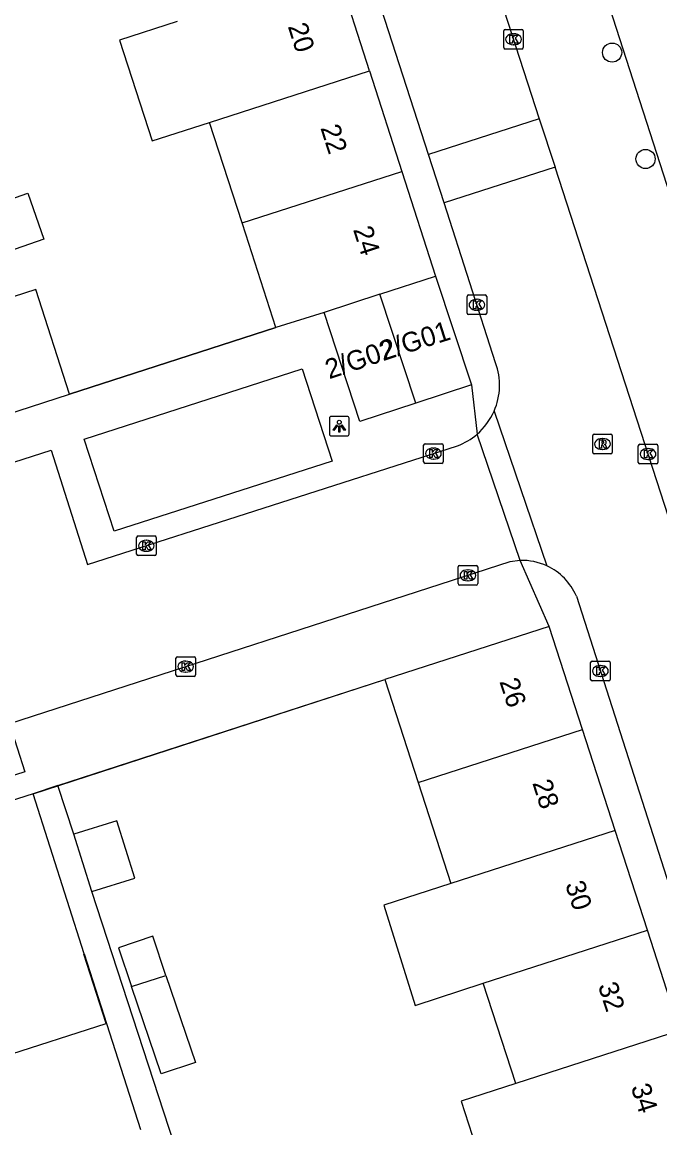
# Model space of a CAD drawing. Extents: x 159377 to 159983, y 382996 to 383595.
# Drawn here: x 159569 to 159601.6, y 383184.3 to 383240.7 of the extents above; entities that cross this region are included whole.
import ezdxf

# ---------------------------------------------------------------- set-up
doc = ezdxf.new("R2010")
doc.units = 0
for name, color, linetype in [('IMGEO_Boom', 7, 'Continuous'), ('IMGEO_Kolk', 7, 'Continuous'), ('IMGEO_Lichtpunt', 7, 'Continuous'), ('IMGEO_Muur', 7, 'Continuous'), ('IMGEO_Pand', 7, 'Continuous'), ('IMGEO_Pand_nummerreeks', 7, 'Continuous'), ('IMGEO_Rijbaan_lokaal_open', 7, 'Continuous'), ('IMGEO_Rioolput', 7, 'Continuous'), ('IMGEO_Voetpad_open', 7, 'Continuous')]:
    doc.layers.add(name, color=color, linetype=linetype)

msp = doc.modelspace()

# ---------------------------------------------------------------- linework, layer by layer
at = {"layer": 'IMGEO_Boom'}
for centre in [(159599.134, 383239.138), (159600.842, 383233.709)]:
    msp.add_circle(centre, 0.489, dxfattribs=at)
at = {"layer": 'IMGEO_Kolk'}
for p, q in [((159593.602, 383239.393), (159593.602, 383240.245)), ((159593.677, 383240.319), (159594.529, 383240.319)), ((159594.09, 383240.099), (159594.115, 383240.099)), ((159594.603, 383240.245), (159594.603, 383239.393)), ((159594.113, 383239.539), (159594.088, 383239.539)), ((159594.529, 383239.319), (159593.677, 383239.319)), ((159591.734, 383225.841), (159591.734, 383226.693)), ((159591.809, 383226.767), (159592.661, 383226.767)), ((159592.222, 383226.547), (159592.247, 383226.547)), ((159592.735, 383226.693), (159592.735, 383225.841)), ((159592.245, 383225.987), (159592.22, 383225.987)), ((159592.661, 383225.767), (159591.809, 383225.767)), ((159589.59, 383219.174), (159590.442, 383219.174)), ((159600.545, 383219.15), (159601.397, 383219.15)), ((159589.515, 383218.248), (159589.515, 383219.1)), ((159590.003, 383218.954), (159590.028, 383218.954)), ((159590.516, 383219.1), (159590.516, 383218.248)), ((159600.47, 383218.224), (159600.47, 383219.076)), ((159600.958, 383218.93), (159600.983, 383218.93)), ((159601.471, 383219.076), (159601.471, 383218.224)), ((159590.442, 383218.174), (159589.59, 383218.174)), ((159590.026, 383218.394), (159590.001, 383218.394)), ((159601.397, 383218.15), (159600.545, 383218.15)), ((159600.981, 383218.37), (159600.956, 383218.37)), ((159574.865, 383213.542), (159574.865, 383214.394)), ((159574.94, 383214.468), (159575.792, 383214.468)), ((159575.353, 383214.248), (159575.378, 383214.248)), ((159575.866, 383214.394), (159575.866, 383213.542)), ((159575.376, 383213.688), (159575.351, 383213.688)), ((159575.792, 383213.468), (159574.94, 383213.468)), ((159591.349, 383212.961), (159592.201, 383212.961)), ((159591.274, 383212.035), (159591.274, 383212.887)), ((159591.762, 383212.741), (159591.787, 383212.741)), ((159592.275, 383212.887), (159592.275, 383212.035)), ((159592.201, 383211.961), (159591.349, 383211.961)), ((159591.785, 383212.181), (159591.76, 383212.181)), ((159576.873, 383207.375), (159576.873, 383208.227)), ((159576.948, 383208.301), (159577.8, 383208.301)), ((159577.361, 383208.081), (159577.386, 383208.081)), ((159577.874, 383208.227), (159577.874, 383207.375)), ((159598.037, 383207.152), (159598.037, 383208.004)), ((159598.112, 383208.078), (159598.964, 383208.078)), ((159598.525, 383207.858), (159598.55, 383207.858)), ((159599.038, 383208.004), (159599.038, 383207.152)), ((159577.8, 383207.301), (159576.948, 383207.301)), ((159577.384, 383207.521), (159577.359, 383207.521)), ((159598.548, 383207.298), (159598.523, 383207.298)), ((159598.964, 383207.078), (159598.112, 383207.078))]:
    msp.add_line(p, q, dxfattribs=at)
for points in [[(159593.602, 383239.393), (159593.602, 383240.245)], [(159593.677, 383240.319), (159594.529, 383240.319)], [(159593.923, 383240.019), (159594.046, 383240.019), (159594.046, 383239.868), (159594.176, 383240.019), (159594.34, 383240.019), (159594.194, 383239.868), (159594.347, 383239.619), (159594.195, 383239.619), (159594.11, 383239.783), (159594.046, 383239.716), (159594.046, 383239.619), (159593.923, 383239.619), (159593.923, 383240.019)], [(159594.603, 383240.245), (159594.603, 383239.393)], [(159594.529, 383239.319), (159593.677, 383239.319)], [(159591.734, 383225.841), (159591.734, 383226.693)], [(159591.809, 383226.767), (159592.661, 383226.767)], [(159592.055, 383226.467), (159592.178, 383226.467), (159592.178, 383226.316), (159592.308, 383226.467), (159592.472, 383226.467), (159592.326, 383226.316), (159592.479, 383226.067), (159592.327, 383226.067), (159592.242, 383226.231), (159592.178, 383226.164), (159592.178, 383226.067), (159592.055, 383226.067), (159592.055, 383226.467)], [(159592.735, 383226.693), (159592.735, 383225.841)], [(159592.661, 383225.767), (159591.809, 383225.767)], [(159589.59, 383219.174), (159590.442, 383219.174)], [(159600.545, 383219.15), (159601.397, 383219.15)], [(159589.515, 383218.248), (159589.515, 383219.1)], [(159589.836, 383218.874), (159589.959, 383218.874), (159589.959, 383218.723), (159590.089, 383218.874), (159590.253, 383218.874), (159590.107, 383218.723), (159590.26, 383218.474), (159590.108, 383218.474), (159590.023, 383218.638), (159589.959, 383218.571), (159589.959, 383218.474), (159589.836, 383218.474), (159589.836, 383218.874)], [(159590.516, 383219.1), (159590.516, 383218.248)], [(159600.47, 383218.224), (159600.47, 383219.076)], [(159600.791, 383218.85), (159600.914, 383218.85), (159600.914, 383218.699), (159601.044, 383218.85), (159601.208, 383218.85), (159601.062, 383218.699), (159601.215, 383218.45), (159601.063, 383218.45), (159600.978, 383218.614), (159600.914, 383218.547), (159600.914, 383218.45), (159600.791, 383218.45), (159600.791, 383218.85)], [(159601.471, 383219.076), (159601.471, 383218.224)], [(159590.442, 383218.174), (159589.59, 383218.174)], [(159601.397, 383218.15), (159600.545, 383218.15)], [(159574.865, 383213.542), (159574.865, 383214.394)], [(159574.94, 383214.468), (159575.792, 383214.468)], [(159575.186, 383214.168), (159575.309, 383214.168), (159575.309, 383214.017), (159575.439, 383214.168), (159575.603, 383214.168), (159575.457, 383214.017), (159575.61, 383213.768), (159575.458, 383213.768), (159575.373, 383213.932), (159575.309, 383213.865), (159575.309, 383213.768), (159575.186, 383213.768), (159575.186, 383214.168)], [(159575.866, 383214.394), (159575.866, 383213.542)], [(159575.792, 383213.468), (159574.94, 383213.468)], [(159591.349, 383212.961), (159592.201, 383212.961)], [(159591.274, 383212.035), (159591.274, 383212.887)], [(159591.595, 383212.661), (159591.718, 383212.661), (159591.718, 383212.51), (159591.848, 383212.661), (159592.012, 383212.661), (159591.866, 383212.51), (159592.019, 383212.261), (159591.867, 383212.261), (159591.782, 383212.425), (159591.718, 383212.358), (159591.718, 383212.261), (159591.595, 383212.261), (159591.595, 383212.661)], [(159592.275, 383212.887), (159592.275, 383212.035)], [(159592.201, 383211.961), (159591.349, 383211.961)], [(159576.873, 383207.375), (159576.873, 383208.227)], [(159576.948, 383208.301), (159577.8, 383208.301)], [(159577.194, 383208.001), (159577.317, 383208.001), (159577.317, 383207.85), (159577.447, 383208.001), (159577.611, 383208.001), (159577.465, 383207.85), (159577.618, 383207.601), (159577.466, 383207.601), (159577.381, 383207.765), (159577.317, 383207.698), (159577.317, 383207.601), (159577.194, 383207.601), (159577.194, 383208.001)], [(159577.874, 383208.227), (159577.874, 383207.375)], [(159598.037, 383207.152), (159598.037, 383208.004)], [(159598.112, 383208.078), (159598.964, 383208.078)], [(159599.038, 383208.004), (159599.038, 383207.152)], [(159577.8, 383207.301), (159576.948, 383207.301)], [(159598.358, 383207.778), (159598.481, 383207.778), (159598.481, 383207.627), (159598.611, 383207.778), (159598.775, 383207.778), (159598.629, 383207.627), (159598.782, 383207.378), (159598.63, 383207.378), (159598.545, 383207.542), (159598.481, 383207.475), (159598.481, 383207.378), (159598.358, 383207.378), (159598.358, 383207.778)], [(159598.964, 383207.078), (159598.112, 383207.078)]]:
    msp.add_lwpolyline(points, dxfattribs=at)
for centre, start, end in [((159593.679, 383240.243), 91.552, 178.448), ((159593.679, 383240.243), 91.552, 178.448), ((159594.527, 383240.243), 1.552, 88.448), ((159594.527, 383240.243), 1.552, 88.448), ((159593.679, 383239.395), 181.552, 268.448), ((159593.679, 383239.395), 181.552, 268.448), ((159594.527, 383239.395), 271.552, 358.448), ((159594.527, 383239.395), 271.552, 358.448), ((159591.811, 383226.691), 91.552, 178.448), ((159591.811, 383226.691), 91.552, 178.448), ((159592.659, 383226.691), 1.552, 88.448), ((159592.659, 383226.691), 1.552, 88.448), ((159591.811, 383225.843), 181.552, 268.448), ((159591.811, 383225.843), 181.552, 268.448), ((159592.659, 383225.843), 271.552, 358.448), ((159592.659, 383225.843), 271.552, 358.448), ((159589.592, 383219.098), 91.552, 178.448), ((159589.592, 383219.098), 91.552, 178.448), ((159590.44, 383219.098), 1.552, 88.448), ((159590.44, 383219.098), 1.552, 88.448), ((159600.547, 383219.074), 91.552, 178.448), ((159600.547, 383219.074), 91.552, 178.448), ((159601.395, 383219.074), 1.552, 88.448), ((159601.395, 383219.074), 1.552, 88.448), ((159589.592, 383218.25), 181.552, 268.448), ((159589.592, 383218.25), 181.552, 268.448), ((159590.44, 383218.25), 271.552, 358.448), ((159590.44, 383218.25), 271.552, 358.448), ((159600.547, 383218.226), 181.552, 268.448), ((159600.547, 383218.226), 181.552, 268.448), ((159601.395, 383218.226), 271.552, 358.448), ((159601.395, 383218.226), 271.552, 358.448), ((159574.942, 383214.392), 91.552, 178.448), ((159574.942, 383214.392), 91.552, 178.448), ((159575.79, 383214.392), 1.552, 88.448), ((159575.79, 383214.392), 1.552, 88.448), ((159574.942, 383213.544), 181.552, 268.448), ((159574.942, 383213.544), 181.552, 268.448), ((159575.79, 383213.544), 271.552, 358.448), ((159575.79, 383213.544), 271.552, 358.448), ((159591.351, 383212.885), 91.552, 178.448), ((159591.351, 383212.885), 91.552, 178.448), ((159592.199, 383212.885), 1.552, 88.448), ((159592.199, 383212.885), 1.552, 88.448), ((159591.351, 383212.037), 181.552, 268.448), ((159591.351, 383212.037), 181.552, 268.448), ((159592.199, 383212.037), 271.552, 358.448), ((159592.199, 383212.037), 271.552, 358.448), ((159576.95, 383208.225), 91.552, 178.448), ((159576.95, 383208.225), 91.552, 178.448), ((159577.798, 383208.225), 1.552, 88.448), ((159577.798, 383208.225), 1.552, 88.448), ((159598.114, 383208.002), 91.552, 178.448), ((159598.114, 383208.002), 91.552, 178.448), ((159598.962, 383208.002), 1.552, 88.448), ((159598.962, 383208.002), 1.552, 88.448), ((159576.95, 383207.377), 181.552, 268.448), ((159576.95, 383207.377), 181.552, 268.448), ((159577.798, 383207.377), 271.552, 358.448), ((159577.798, 383207.377), 271.552, 358.448), ((159598.114, 383207.154), 181.552, 268.448), ((159598.114, 383207.154), 181.552, 268.448), ((159598.962, 383207.154), 271.552, 358.448), ((159598.962, 383207.154), 271.552, 358.448)]:
    msp.add_arc(centre, 0.0765, start, end, dxfattribs=at)
for centre, major_axis, ratio, start_param, end_param in [((159594.089, 383239.819), (-0.387, 0.002), 0.722429, 4.712389, 7.853982), ((159594.114, 383239.819), (-0.39, 0.002), 0.717154, 1.570796, 4.712389), ((159592.221, 383226.267), (-0.387, 0.002), 0.722429, 4.712389, 7.853982), ((159592.246, 383226.267), (-0.39, 0.002), 0.717154, 1.570796, 4.712389), ((159590.002, 383218.674), (-0.387, 0.002), 0.722429, 4.712389, 7.853982), ((159590.027, 383218.674), (-0.39, 0.002), 0.717154, 1.570796, 4.712389), ((159600.957, 383218.65), (-0.387, 0.002), 0.722429, 4.712389, 7.853982), ((159600.982, 383218.65), (-0.39, 0.002), 0.717154, 1.570796, 4.712389), ((159575.352, 383213.968), (-0.387, 0.002), 0.722429, 4.712389, 7.853982), ((159575.377, 383213.968), (-0.39, 0.002), 0.717154, 1.570796, 4.712389), ((159591.761, 383212.461), (-0.387, 0.002), 0.722429, 4.712389, 7.853982), ((159591.786, 383212.461), (-0.39, 0.002), 0.717154, 1.570796, 4.712389), ((159577.36, 383207.801), (-0.387, 0.002), 0.722429, 4.712389, 7.853982), ((159577.385, 383207.801), (-0.39, 0.002), 0.717154, 1.570796, 4.712389), ((159598.524, 383207.578), (-0.387, 0.002), 0.722429, 4.712389, 7.853982), ((159598.549, 383207.578), (-0.39, 0.002), 0.717154, 1.570796, 4.712389)]:
    msp.add_ellipse(centre, major_axis=major_axis, ratio=ratio, start_param=start_param, end_param=end_param, dxfattribs=at)
at = {"layer": 'IMGEO_Lichtpunt'}
for p, q in [((159584.712, 383220.474), (159584.712, 383219.667)), ((159584.712, 383220.474), (159584.712, 383219.667)), ((159585.614, 383220.569), (159584.806, 383220.569)), ((159585.614, 383220.569), (159584.806, 383220.569)), ((159585.708, 383219.667), (159585.708, 383220.474)), ((159585.708, 383219.667), (159585.708, 383220.474)), ((159584.806, 383219.573), (159585.614, 383219.573)), ((159584.806, 383219.573), (159585.614, 383219.573))]:
    msp.add_line(p, q, dxfattribs=at)
for points in [[(159585.086, 383220.138), (159585.125, 383220.11), (159584.937, 383219.848), (159584.899, 383219.875), (159585.086, 383220.138)], [(159585.188, 383220.09), (159585.235, 383220.09), (159585.235, 383219.768), (159585.188, 383219.768), (159585.188, 383220.09)], [(159585.298, 383220.11), (159585.336, 383220.137), (159585.523, 383219.875), (159585.484, 383219.847), (159585.298, 383220.11)]]:
    msp.add_lwpolyline(points, dxfattribs=at)
msp.add_circle((159585.211, 383220.272), 0.0994, dxfattribs=at)
for centre, start, end in [((159584.806, 383220.474), 90, 180), ((159584.806, 383220.474), 90, 180), ((159585.614, 383220.474), 0, 90), ((159585.614, 383220.474), 0, 90), ((159584.806, 383219.667), 180, 270), ((159584.806, 383219.667), 180, 270), ((159585.614, 383219.667), 270, 0), ((159585.614, 383219.667), 270, 360)]:
    msp.add_arc(centre, 0.0946, start, end, dxfattribs=at)
at = {"layer": 'IMGEO_Muur'}
for points in [[(159571.447, 383221.705), (159581.974, 383225.106)], [(159569.587, 383201.314), (159587.539, 383207.143)]]:
    msp.add_lwpolyline(points, dxfattribs=at)
at = {"layer": 'IMGEO_Pand'}
for points in [[(159586.752, 383238.201), (159585.097, 383243.354)], [(159576.933, 383240.724), (159574, 383239.779), (159575.659, 383234.63), (159578.595, 383235.575)], [(159578.595, 383235.575), (159586.752, 383238.201)], [(159586.752, 383238.201), (159588.402, 383233.069)], [(159580.251, 383230.443), (159578.595, 383235.575)], [(159580.251, 383230.443), (159588.402, 383233.069)], [(159588.402, 383233.069), (159590.116, 383227.736)], [(159569.319, 383231.964), (159570.14, 383229.617), (159567.941, 383228.848), (159567.12, 383231.195), (159569.319, 383231.964)], [(159581.974, 383225.106), (159580.438, 383229.865), (159580.251, 383230.443)], [(159587.276, 383226.815), (159590.116, 383227.736)], [(159590.116, 383227.736), (159591.966, 383222.185)], [(159571.447, 383221.705), (159569.717, 383227.049), (159567.34, 383226.283)], [(159587.276, 383226.815), (159584.434, 383225.871)], [(159589.114, 383221.244), (159587.276, 383226.815)], [(159584.434, 383225.871), (159581.974, 383225.106)], [(159589.114, 383221.244), (159586.261, 383220.303), (159584.434, 383225.871)], [(159565.818, 383223.436), (159566.861, 383220.219), (159571.447, 383221.705)], [(159591.966, 383222.185), (159589.114, 383221.244)], [(159595.914, 383209.856), (159587.539, 383207.143)], [(159597.617, 383204.596), (159595.914, 383209.856)], [(159587.539, 383207.143), (159589.24, 383201.89)], [(159589.24, 383201.89), (159597.617, 383204.596)], [(159599.287, 383199.441), (159597.617, 383204.596)], [(159589.24, 383201.89), (159590.909, 383196.737)], [(159569.587, 383201.314), (159564.189, 383199.583)], [(159572.197, 383193.137), (159569.587, 383201.314)], [(159572.587, 383196.317), (159574.778, 383197.01), (159573.852, 383199.938), (159571.66, 383199.245)], [(159599.287, 383199.441), (159590.909, 383196.737)], [(159600.938, 383194.343), (159599.287, 383199.441)], [(159572.587, 383196.317), (159571.66, 383199.245)], [(159590.909, 383196.737), (159587.489, 383195.62), (159589.076, 383190.501), (159592.56, 383191.638)], [(159592.56, 383191.638), (159600.938, 383194.343)], [(159602.595, 383189.226), (159600.938, 383194.343)], [(159576.366, 383192.043), (159575.689, 383194.042), (159573.939, 383193.449), (159574.608, 383191.476)], [(159568.017, 383187.893), (159573.31, 383189.59), (159572.175, 383193.13), (159572.197, 383193.137)], [(159574.608, 383191.476), (159576.366, 383192.043)], [(159576.366, 383192.043), (159577.87, 383187.603), (159576.12, 383187.011), (159574.608, 383191.476)], [(159594.217, 383186.522), (159592.56, 383191.638)], [(159602.595, 383189.226), (159594.217, 383186.522)], [(159594.217, 383186.522), (159591.435, 383185.624), (159593.118, 383180.411), (159595.904, 383181.31)]]:
    msp.add_lwpolyline(points, dxfattribs=at)
at = {"layer": 'IMGEO_Rijbaan_lokaal_open'}
for points in [[(159585.361, 383266.81), (159590.799, 383250), (159595.419, 383235.761)], [(159589.762, 383233.936), (159584.58, 383250), (159579.729, 383264.98)], [(159595.419, 383235.761), (159589.762, 383233.936)], [(159595.419, 383235.761), (159596.221, 383233.289)], [(159590.56, 383231.462), (159589.762, 383233.936)], [(159596.221, 383233.289), (159590.56, 383231.462)], [(159607.802, 383197.595), (159596.221, 383233.289)], [(159593.192, 383223.303), (159590.56, 383231.462)], [(159528.425, 383210.177), (159564.747, 383221.794), (159566.151, 383217.448), (159570.5, 383218.852), (159572.368, 383213.005), (159591.243, 383219.067)], [(159593.112, 383220.84), (159595.806, 383212.941)], [(159594.442, 383213.217), (159592.24, 383219.664)], [(159594.442, 383213.217), (159593.923, 383213.154), (159568.377, 383204.889), (159569.171, 383202.429), (159543.044, 383194.025)], [(159597.309, 383211.405), (159602.34, 383195.729)]]:
    msp.add_lwpolyline(points, dxfattribs=at)
for centre, radius, start, end in [((159590.112, 383222.17), 3.281, 336.0849, 20.1944), ((159590.045, 383222.203), 3.356, 310.8452, 336.0412), ((159590.052, 383222.187), 3.34, 290.8933, 310.9327), ((159594.544, 383210.211), 3.008, 65.1862, 91.9355), ((159594.541, 383210.199), 3.02, 23.5323, 65.2234)]:
    msp.add_arc(centre, radius, start, end, dxfattribs=at)
at = {"layer": 'IMGEO_Rioolput'}
for p, q in [((159598.143, 383218.737), (159598.143, 383219.589)), ((159598.218, 383219.663), (159599.07, 383219.663)), ((159598.631, 383219.443), (159598.656, 383219.443)), ((159599.144, 383219.589), (159599.144, 383218.737)), ((159599.07, 383218.663), (159598.218, 383218.663)), ((159598.654, 383218.883), (159598.629, 383218.883))]:
    msp.add_line(p, q, dxfattribs=at)
for points in [[(159598.143, 383218.737), (159598.143, 383219.589)], [(159598.218, 383219.663), (159599.07, 383219.663)], [(159598.732, 383219.361), (159598.48, 383219.363), (159598.48, 383218.963)], [(159598.658, 383219.282), (159598.604, 383219.282), (159598.604, 383219.201)], [(159598.604, 383219.201), (159598.656, 383219.201)], [(159599.144, 383219.589), (159599.144, 383218.737)], [(159599.07, 383218.663), (159598.218, 383218.663)], [(159598.48, 383218.963), (159598.604, 383218.963), (159598.604, 383219.125), (159598.615, 383219.125)], [(159598.662, 383219.096), (159598.733, 383218.963), (159598.873, 383218.963), (159598.808, 383219.089)]]:
    msp.add_lwpolyline(points, dxfattribs=at)
for centre, radius, start, end in [((159598.22, 383219.587), 0.0765, 91.552, 178.448), ((159598.22, 383219.587), 0.0765, 91.552, 178.448), ((159598.64, 383219.39), 0.19, 274.7715, 282.9687), ((159598.664, 383219.186), 0.0964, 77.0061, 93.1865), ((159598.678, 383219.243), 0.0378, 276.6634, 79.6772), ((159598.731, 383219.251), 0.109, 350.3612, 89.416), ((159598.729, 383219.251), 0.112, 277.5842, 350.9817), ((159598.713, 383219.036), 0.108, 29.5134, 73.7905), ((159599.068, 383219.587), 0.0765, 1.552, 88.448), ((159599.068, 383219.587), 0.0765, 1.552, 88.448), ((159598.22, 383218.739), 0.0765, 181.552, 268.448), ((159598.22, 383218.739), 0.0765, 181.552, 268.448), ((159598.614, 383219.072), 0.0533, 26.0293, 88.6989), ((159599.068, 383218.739), 0.0765, 271.552, 358.448), ((159599.068, 383218.739), 0.0765, 271.552, 358.448)]:
    msp.add_arc(centre, radius, start, end, dxfattribs=at)
for centre, major_axis, ratio, start_param, end_param in [((159598.63, 383219.163), (-0.387, 0.002), 0.722429, 4.712389, 7.853982), ((159598.655, 383219.163), (-0.39, 0.002), 0.717154, 1.570796, 4.712389)]:
    msp.add_ellipse(centre, major_axis=major_axis, ratio=ratio, start_param=start_param, end_param=end_param, dxfattribs=at)
at = {"layer": 'IMGEO_Voetpad_open'}
for points in [[(159591.98, 383263.245), (159596.25, 383250), (159612.043, 383200.997), (159609.174, 383200.07)], [(159581.974, 383225.106), (159571.447, 383221.705)], [(159572.199, 383219.405), (159583.31, 383222.996), (159584.855, 383218.28), (159573.724, 383214.708), (159572.199, 383219.405)], [(159591.966, 383222.185), (159592.24, 383219.664)], [(159595.914, 383209.856), (159594.442, 383213.217)], [(159570.855, 383201.726), (159587.539, 383207.143)], [(159570.855, 383201.726), (159569.587, 383201.314)], [(159571.66, 383199.245), (159570.855, 383201.726)], [(159583.345, 383163.314), (159572.587, 383196.317)], [(159572.197, 383193.137), (159575.068, 383184.185)]]:
    msp.add_lwpolyline(points, dxfattribs=at)

# ---------------------------------------------------------------- texts
at = {"layer": 'IMGEO_Pand_nummerreeks'}
for s, rotation, p in [('20', 287.813, (159582.576, 383240.477)), ('22', 287.815, (159584.24, 383235.298)), ('24', 287.815, (159585.907, 383230.111)), ('2/G01', 17.5457, (159587.489, 383223.417)), ('2/G02', 18.5631, (159584.695, 383222.462)), ('26', 287.9431, (159593.376, 383207.044)), ('28', 287.9431, (159595.053, 383201.866)), ('30', 287.9431, (159596.729, 383196.69)), ('32', 287.9431, (159598.403, 383191.521)), ('34', 287.9448, (159600.081, 383186.343))]:
    msp.add_text(s, height=1, rotation=rotation, dxfattribs=at).set_placement(p)

doc.saveas('drawing.dxf')
